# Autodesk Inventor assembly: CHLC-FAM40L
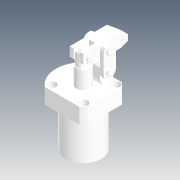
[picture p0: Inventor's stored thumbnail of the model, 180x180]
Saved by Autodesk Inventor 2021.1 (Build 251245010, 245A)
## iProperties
Company: Microsoft
Created: 2019-11
Part Number: CHLC-FAM40L
Description: STEP AP214
Document SubType Name: Assembly
Designer: user
Title: CHLC-FAM40L.STEP
Author: Windows
Revision Number: ÈÎºÎ
Sending System: SolidWorks 2015
Preprocessor: SwSTEP 2.0
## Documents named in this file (11)
- D:\Vault_2016\Projekty\Clamptek\Hydraulic\CHLC\CHLC-40\Inventor\CHLC-FAM40L\CHLC-FAM40L.iam
- D:\Vault_2016\Projekty\Clamptek\Hydraulic\CHLC\CHLC-40\Inventor\CHLC-FAM40L\CHLC-FAM40±¾Ìå.ipt
- D:\Vault_2016\Projekty\Clamptek\Hydraulic\CHLC\CHLC-40\Inventor\CHLC-FAM40L\CHLC-40-01.ipt
- D:\Vault_2016\Projekty\Clamptek\Hydraulic\CHLC\CHLC-40\Inventor\CHLC-FAM40L\CHLC-40-02.ipt
- D:\Vault_2016\Projekty\Clamptek\Hydraulic\CHLC\CHLC-40\Inventor\CHLC-FAM40L\CHLC-40-03.ipt
- D:\Vault_2016\Projekty\Clamptek\Hydraulic\CHLC\CHLC-40\Inventor\CHLC-FAM40L\CHLC-40-04.ipt
- D:\Vault_2016\Projekty\Clamptek\Hydraulic\CHLC\CHLC-40\Inventor\CHLC-FAM40L\CHLC-40-06.ipt
- D:\Vault_2016\Projekty\Clamptek\Hydraulic\CHLC\CHLC-40\Inventor\CHLC-FAM40L\CHLC-40-08.ipt
- D:\Vault_2016\Projekty\Clamptek\Hydraulic\CHLC\CHLC-40\Inventor\CHLC-FAM40L\HANJIE.ipt
- D:\Vault_2016\Projekty\Clamptek\Hydraulic\CHLC\CHLC-40\Inventor\CHLC-FAM40L\ZHICHENGKUAI.ipt
- D:\Vault_2016\Projekty\Clamptek\Hydraulic\CHLC\CHLC-40\Inventor\CHLC-FAM40L\M6LS.ipt
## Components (18 placed, 18 different names)
1. CHLC-FAM40±¾Ìå_1
2. CHLC-40-01_2
3. CHLC-40-02_3
4. CHLC-40-03_4
5. CHLC-40-04_5
6. CHLC-40-06_6
7. CHLC-40-08_7
8. HANJIE_8
9. ZHICHENGKUAI_9
10. CHLC-40-03_10
11. CHLC-40-06_11
12. CHLC-40-06_12
13. CHLC-40-06_13
14. CHLC-40-06_14
15. CHLC-40-06_15
16. CHLC-40-02_16
17. M6LS_17
18. M6LS_18
